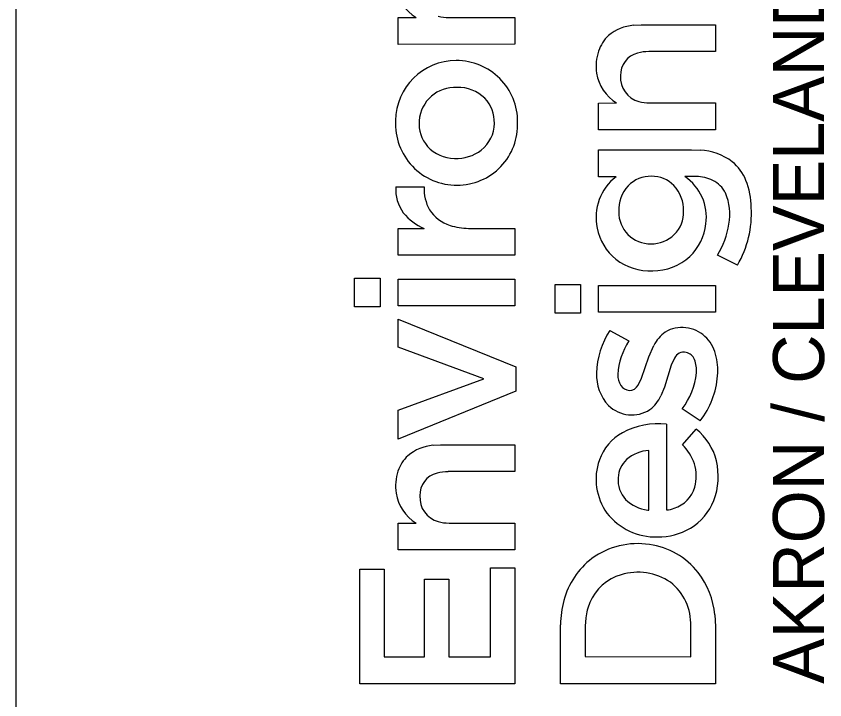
# Model space of a CAD drawing. Extents: x -0.4 to 34, y 0 to 22.
# Drawn here: x 32 to 32.901, y 3.12 to 3.882 of the extents above; entities that cross this region are included whole.
import ezdxf

# ---------------------------------------------------------------- set-up
doc = ezdxf.new("R2010")
doc.units = 0
doc.layers.add('SH_Border', color=7, linetype='Continuous')
doc.layers.add('SH_Cut_Line', color=7, linetype='Continuous')

msp = doc.modelspace()

# ---------------------------------------------------------------- linework, layer by layer
at = {"layer": 'SH_Border'}
msp.add_line((32, 0.5), (32, 21.5), dxfattribs=at)
at = {"layer": 'SH_Cut_Line'}
for p, q in [((32.42542, 3.88066), (32.44552, 3.88071)), ((32.42542, 3.85086), (32.42542, 3.88066)), ((32.48222, 3.88071), (32.55569, 3.88071)), ((32.55569, 3.88071), (32.55571, 3.85096)), ((32.68784, 3.8722), (32.69634, 3.87266)), ((32.69634, 3.87266), (32.77916, 3.87266)), ((32.77916, 3.87266), (32.77917, 3.84287)), ((32.55571, 3.85096), (32.42542, 3.85086)), ((32.77917, 3.84287), (32.70485, 3.8428)), ((32.64888, 3.7855), (32.66897, 3.78555)), ((32.64888, 3.75569), (32.64888, 3.7855)), ((32.70568, 3.78555), (32.77915, 3.78555)), ((32.77915, 3.78555), (32.77917, 3.75579)), ((32.77917, 3.75579), (32.64888, 3.75569)), ((32.6489, 3.70336), (32.64889, 3.73322)), ((32.64889, 3.73322), (32.75236, 3.73322)), ((32.75236, 3.73322), (32.76191, 3.73285)), ((32.66836, 3.70336), (32.6489, 3.70336)), ((32.75763, 3.70356), (32.74487, 3.70361)), ((32.42299, 3.69193), (32.45454, 3.69193)), ((32.42542, 3.64577), (32.45473, 3.64579)), ((32.42542, 3.61593), (32.42542, 3.64577)), ((32.50413, 3.64581), (32.55571, 3.64573)), ((32.55571, 3.64573), (32.55565, 3.61593)), ((32.55565, 3.61593), (32.42542, 3.61593)), ((32.8036, 3.60491), (32.7812, 3.61598)), ((32.37705, 3.55818), (32.37705, 3.59026)), ((32.37705, 3.59026), (32.40543, 3.59026)), ((32.40543, 3.59026), (32.40543, 3.55818)), ((32.42542, 3.55942), (32.42542, 3.58928)), ((32.42542, 3.58928), (32.55571, 3.58928)), ((32.55571, 3.58928), (32.55571, 3.55942)), ((32.60051, 3.55111), (32.60051, 3.58319)), ((32.60051, 3.58319), (32.62889, 3.58319)), ((32.62889, 3.58319), (32.62889, 3.55111)), ((32.64888, 3.55234), (32.64888, 3.5822)), ((32.64888, 3.5822), (32.77917, 3.5822)), ((32.77917, 3.5822), (32.77917, 3.55234)), ((32.55571, 3.55942), (32.42542, 3.55942)), ((32.40543, 3.55818), (32.37705, 3.55818)), ((32.62889, 3.55111), (32.60051, 3.55111)), ((32.77917, 3.55234), (32.64888, 3.55234)), ((32.42542, 3.51327), (32.42542, 3.5446)), ((32.42542, 3.5446), (32.5567, 3.4913)), ((32.66151, 3.53207), (32.68268, 3.52025)), ((32.70483, 3.50258), (32.71036, 3.51526)), ((32.52117, 3.47798), (32.42542, 3.51327)), ((32.69675, 3.47868), (32.70483, 3.50258)), ((32.73342, 3.50101), (32.72985, 3.4933)), ((32.5567, 3.4913), (32.5567, 3.46441)), ((32.72985, 3.4933), (32.72213, 3.46882)), ((32.42542, 3.44294), (32.52117, 3.47798)), ((32.69299, 3.47117), (32.69675, 3.47868)), ((32.72213, 3.46882), (32.71822, 3.45921)), ((32.5567, 3.46441), (32.42542, 3.41086)), ((32.42542, 3.41086), (32.42542, 3.44294)), ((32.76214, 3.43141), (32.74198, 3.44469)), ((32.72453, 3.42747), (32.72463, 3.33195)), ((32.74228, 3.40465), (32.75768, 3.422)), ((32.46439, 3.40397), (32.47289, 3.40443)), ((32.47289, 3.40443), (32.55571, 3.40443)), ((32.55571, 3.40443), (32.55571, 3.37465)), ((32.70489, 3.33182), (32.70489, 3.39834)), ((32.55571, 3.37465), (32.4814, 3.37457)), ((32.70361, 3.33165), (32.70489, 3.33182)), ((32.42542, 3.31728), (32.44552, 3.31733)), ((32.42542, 3.28747), (32.42542, 3.31728)), ((32.48222, 3.31733), (32.55569, 3.31733)), ((32.55569, 3.31733), (32.55571, 3.28756)), ((32.55571, 3.28756), (32.42542, 3.28747)), ((32.38298, 3.13791), (32.38298, 3.26598)), ((32.38298, 3.26598), (32.41012, 3.26598)), ((32.41012, 3.26598), (32.41012, 3.16827)), ((32.52857, 3.16827), (32.52857, 3.26722)), ((32.52857, 3.26722), (32.55571, 3.26722)), ((32.55571, 3.26722), (32.55571, 3.13791)), ((32.45503, 3.16827), (32.45503, 3.25488)), ((32.45503, 3.25488), (32.48218, 3.25488)), ((32.48218, 3.25488), (32.48218, 3.16827)), ((32.63465, 3.21178), (32.63407, 3.2023)), ((32.77847, 3.21497), (32.77917, 3.2021)), ((32.60643, 3.13799), (32.60644, 3.204)), ((32.63407, 3.2023), (32.63407, 3.16838)), ((32.75149, 3.16834), (32.75153, 3.20239)), ((32.77917, 3.2021), (32.77917, 3.138)), ((32.41012, 3.16827), (32.45503, 3.16827)), ((32.48218, 3.16827), (32.52857, 3.16827)), ((32.63407, 3.16838), (32.75149, 3.16834)), ((32.55571, 3.13791), (32.38298, 3.13791)), ((32.77917, 3.138), (32.60643, 3.13799))]:
    msp.add_line(p, q, dxfattribs=at)
for points in [[(32.42542, 3.85086), (32.42542, 3.88066), (32.44552, 3.88071)], [(32.48222, 3.88071), (32.55569, 3.88071), (32.55571, 3.85096), (32.42542, 3.85086)], [(32.68784, 3.8722), (32.69634, 3.87266), (32.77916, 3.87266), (32.77917, 3.84287), (32.70485, 3.8428)], [(32.64888, 3.75569), (32.64888, 3.7855), (32.66897, 3.78555)], [(32.70568, 3.78555), (32.77915, 3.78555), (32.77917, 3.75579), (32.64888, 3.75569)], [(32.66836, 3.70336), (32.6489, 3.70336), (32.64889, 3.73322), (32.75236, 3.73322), (32.76191, 3.73285)], [(32.75763, 3.70356), (32.74487, 3.70361)], [(32.42299, 3.69193), (32.45454, 3.69193)], [(32.50413, 3.64581), (32.55571, 3.64573), (32.55565, 3.61593), (32.42542, 3.61593)], [(32.42542, 3.61593), (32.42542, 3.64577), (32.45473, 3.64579)], [(32.8036, 3.60491), (32.7812, 3.61598)], [(32.66151, 3.53207), (32.68268, 3.52025)], [(32.69299, 3.47117), (32.69675, 3.47868), (32.70483, 3.50258), (32.71036, 3.51526)], [(32.73342, 3.50101), (32.72985, 3.4933), (32.72213, 3.46882), (32.71822, 3.45921)], [(32.76214, 3.43141), (32.74198, 3.44469)], [(32.72453, 3.42747), (32.72463, 3.33195)], [(32.74228, 3.40465), (32.75768, 3.422)], [(32.46439, 3.40397), (32.47289, 3.40443), (32.55571, 3.40443), (32.55571, 3.37465), (32.4814, 3.37457)], [(32.70361, 3.33165), (32.70489, 3.33182), (32.70489, 3.39834)], [(32.42542, 3.28747), (32.42542, 3.31728), (32.44552, 3.31733)], [(32.48222, 3.31733), (32.55569, 3.31733), (32.55571, 3.28756), (32.42542, 3.28747)], [(32.77847, 3.21497), (32.77917, 3.2021), (32.77917, 3.138), (32.60643, 3.13799)], [(32.63465, 3.21178), (32.63407, 3.2023), (32.63407, 3.16838), (32.75149, 3.16834), (32.75153, 3.20239)], [(32.60643, 3.13799), (32.60644, 3.204)]]:
    msp.add_lwpolyline(points, dxfattribs=at)
for points in [[(32.37705, 3.55818), (32.37705, 3.59026), (32.40543, 3.59026), (32.40543, 3.55818)], [(32.42542, 3.55942), (32.42542, 3.58928), (32.55571, 3.58928), (32.55571, 3.55942)], [(32.60051, 3.55111), (32.60051, 3.58319), (32.62889, 3.58319), (32.62889, 3.55111)], [(32.64888, 3.55234), (32.64888, 3.5822), (32.77917, 3.5822), (32.77917, 3.55234)], [(32.42542, 3.41086), (32.42542, 3.44294), (32.52117, 3.47798), (32.42542, 3.51327), (32.42542, 3.5446), (32.5567, 3.4913), (32.5567, 3.46441)], [(32.38298, 3.13791), (32.38298, 3.26598), (32.41012, 3.26598), (32.41012, 3.16827), (32.45503, 3.16827), (32.45503, 3.25488), (32.48218, 3.25488), (32.48218, 3.16827), (32.52857, 3.16827), (32.52857, 3.26722), (32.55571, 3.26722), (32.55571, 3.13791)]]:
    msp.add_lwpolyline(points, close=True, dxfattribs=at)
for centre, radius, start, end in [((32.47027, 3.92141), 0.04763, 188.96462, 238.69865), ((32.47027, 3.92141), 0.04763, 188.96462, 238.69865), ((32.48183, 3.92286), 0.04215, 254.08913, 270.52838), ((32.48183, 3.92286), 0.04215, 254.08913, 270.52838), ((32.69216, 3.82251), 0.04988, 94.97056, 130.22484), ((32.69216, 3.82251), 0.04988, 94.97056, 130.22484), ((32.68694, 3.83085), 0.04016, 132.22383, 161.68229), ((32.68694, 3.83085), 0.04016, 132.22383, 161.68229), ((32.70217, 3.82642), 0.05602, 162.27398, 187.79173), ((32.70217, 3.82642), 0.05602, 162.27398, 187.79173), ((32.69828, 3.81689), 0.02498, 103.68683, 182.21395), ((32.69828, 3.81689), 0.02498, 103.68683, 182.21395), ((32.70453, 3.79679), 0.04601, 89.60515, 105.33026), ((32.70453, 3.79679), 0.04601, 89.60515, 105.33026), ((32.49014, 3.76543), 0.0674, 89.84756, 179.64047), ((32.49014, 3.76543), 0.0674, 89.84756, 179.64047), ((32.49057, 3.76474), 0.0681, 359.54009, 90.21138), ((32.49057, 3.76474), 0.0681, 359.54009, 90.21138), ((32.69372, 3.82624), 0.04763, 188.96462, 238.69865), ((32.69372, 3.82624), 0.04763, 188.96462, 238.69865), ((32.7008, 3.81381), 0.02757, 175.58441, 255.13816), ((32.7008, 3.81381), 0.02757, 175.58441, 255.13816), ((32.48923, 3.76263), 0.0404, 87.04809, 175.57259), ((32.48923, 3.76263), 0.0404, 87.04809, 175.57259), ((32.49204, 3.75999), 0.04299, 45.84264, 90.98008), ((32.49204, 3.75999), 0.04299, 45.84264, 90.98008), ((32.49458, 3.76421), 0.03821, 357.88569, 44.15902), ((32.49458, 3.76421), 0.03821, 357.88569, 44.15902), ((32.70529, 3.82769), 0.04215, 254.08913, 270.52838), ((32.70529, 3.82769), 0.04215, 254.08913, 270.52838), ((32.49083, 3.76209), 0.06819, 176.8344, 270.40384), ((32.49083, 3.76209), 0.06819, 176.8344, 270.40384), ((32.48729, 3.7625), 0.03848, 175.15378, 221.14706), ((32.48729, 3.7625), 0.03848, 175.15378, 221.14706), ((32.49123, 3.76139), 0.06749, 270.06243, 2.37759), ((32.49123, 3.76139), 0.06749, 270.06243, 2.37759), ((32.49446, 3.76318), 0.0383, 308.28936, 359.43468), ((32.49446, 3.76318), 0.0383, 308.28936, 359.43468), ((32.48919, 3.76607), 0.04228, 223.09994, 268.80895), ((32.48919, 3.76607), 0.04228, 223.09994, 268.80895), ((32.49096, 3.7679), 0.04418, 266.56515, 308.06078), ((32.49096, 3.7679), 0.04418, 266.56515, 308.06078), ((32.75907, 3.66789), 0.06503, 53.40344, 87.49062), ((32.75907, 3.66789), 0.06503, 53.40344, 87.49062), ((32.76517, 3.68039), 0.05141, 21.60748, 50.5577), ((32.76517, 3.68039), 0.05141, 21.60748, 50.5577), ((32.70292, 3.65813), 0.05692, 127.37482, 192.22468), ((32.70292, 3.65813), 0.05692, 127.37482, 192.22468), ((32.70693, 3.66927), 0.0346, 88.47302, 136.42562), ((32.70693, 3.66927), 0.0346, 88.47302, 136.42562), ((32.70814, 3.66963), 0.03424, 44.27195, 90.47623), ((32.70814, 3.66963), 0.03424, 44.27195, 90.47623), ((32.71421, 3.65829), 0.05472, 352.1125, 55.92295), ((32.71421, 3.65829), 0.05472, 352.1125, 55.92295), ((32.75666, 3.65725), 0.04633, 65.01687, 88.8011), ((32.75666, 3.65725), 0.04633, 65.01687, 88.8011), ((32.7626, 3.67155), 0.03085, 26.26808, 63.80301), ((32.7626, 3.67155), 0.03085, 26.26808, 63.80301), ((32.73069, 3.66714), 0.08835, 1.15143, 21.3627), ((32.73069, 3.66714), 0.08835, 1.15143, 21.3627), ((32.46616, 3.68882), 0.04329, 175.87313, 216.34747), ((32.46616, 3.68882), 0.04329, 175.87313, 216.34747), ((32.50087, 3.68948), 0.04639, 176.9688, 209.60636), ((32.50087, 3.68948), 0.04639, 176.9688, 209.60636), ((32.71141, 3.66602), 0.0401, 137.46739, 182.33237), ((32.71141, 3.66602), 0.0401, 137.46739, 182.33237), ((32.70368, 3.666), 0.03996, 358.57141, 43.53765), ((32.70368, 3.666), 0.03996, 358.57141, 43.53765), ((32.73565, 3.66154), 0.05953, 349.30734, 23.43071), ((32.73565, 3.66154), 0.05953, 349.30734, 23.43071), ((32.70538, 3.66244), 0.11383, 329.6388, 3.25998), ((32.70538, 3.66244), 0.11383, 329.6388, 3.25998), ((32.47466, 3.69716), 0.05511, 218.09809, 248.7907), ((32.47466, 3.69716), 0.05511, 218.09809, 248.7907), ((32.49514, 3.68814), 0.04079, 211.94466, 253.2028), ((32.49514, 3.68814), 0.04079, 211.94466, 253.2028), ((32.70645, 3.6637), 0.03511, 178.88208, 271.08374), ((32.70645, 3.6637), 0.03511, 178.88208, 271.08374), ((32.70818, 3.66404), 0.03546, 268.27882, 1.55016), ((32.70818, 3.66404), 0.03546, 268.27882, 1.55016), ((32.50465, 3.7165), 0.07069, 252.46555, 269.57296), ((32.50465, 3.7165), 0.07069, 252.46555, 269.57296), ((32.70988, 3.65708), 0.05887, 313.74196, 353.8554), ((32.70988, 3.65708), 0.05887, 313.74196, 353.8554), ((32.70738, 3.66334), 0.08771, 327.31495, 351.57478), ((32.70738, 3.66334), 0.08771, 327.31495, 351.57478), ((32.70463, 3.65696), 0.05837, 190.75182, 231.28919), ((32.70463, 3.65696), 0.05837, 190.75182, 231.28919), ((32.70954, 3.65901), 0.06051, 269.6361, 312.70877), ((32.70954, 3.65901), 0.06051, 269.6361, 312.70877), ((32.70632, 3.66112), 0.06269, 232.46061, 272.59022), ((32.70632, 3.66112), 0.06269, 232.46061, 272.59022), ((32.73636, 3.48258), 0.08973, 146.53104, 178.7571), ((32.73636, 3.48258), 0.08973, 146.53104, 178.7571), ((32.7406, 3.5026), 0.03263, 80.17192, 122.51969), ((32.7406, 3.5026), 0.03263, 80.17192, 122.51969), ((32.74278, 3.49824), 0.03667, 47.79344, 84.68918), ((32.74278, 3.49824), 0.03667, 47.79344, 84.68918), ((32.74661, 3.49713), 0.04053, 125.51182, 153.41595), ((32.74661, 3.49713), 0.04053, 125.51182, 153.41595), ((32.73788, 3.4946), 0.04267, 14.9966, 46.20632), ((32.73788, 3.4946), 0.04267, 14.9966, 46.20632), ((32.74519, 3.4789), 0.07495, 146.51121, 176.91007), ((32.74519, 3.4789), 0.07495, 146.51121, 176.91007), ((32.74384, 3.49631), 0.01143, 76.66094, 155.7053), ((32.74384, 3.49631), 0.01143, 76.66094, 155.7053), ((32.74397, 3.49511), 0.01256, 21.5098, 78.52618), ((32.74397, 3.49511), 0.01256, 21.5098, 78.52618), ((32.71044, 3.48674), 0.07121, 355.83062, 15.39138), ((32.71044, 3.48674), 0.07121, 355.83062, 15.39138), ((32.72592, 3.48766), 0.03209, 354.57264, 22.06805), ((32.72592, 3.48766), 0.03209, 354.57264, 22.06805), ((32.69666, 3.48238), 0.05005, 177.53659, 222.79318), ((32.69666, 3.48238), 0.05005, 177.53659, 222.79318), ((32.6931, 3.48233), 0.02276, 178.47474, 211.08679), ((32.6931, 3.48233), 0.02276, 178.47474, 211.08679), ((32.68248, 3.49149), 0.0757, 321.81101, 354.79685), ((32.68248, 3.49149), 0.0757, 321.81101, 354.79685), ((32.68952, 3.4882), 0.09219, 321.9777, 355.87384), ((32.68952, 3.4882), 0.09219, 321.9777, 355.87384), ((32.68331, 3.4767), 0.01148, 212.23676, 268.37769), ((32.68331, 3.4767), 0.01148, 212.23676, 268.37769), ((32.68342, 3.47589), 0.01067, 267.71603, 333.73375), ((32.68342, 3.47589), 0.01067, 267.71603, 333.73375), ((32.68098, 3.4758), 0.04077, 308.08772, 335.98736), ((32.68098, 3.4758), 0.04077, 308.08772, 335.98736), ((32.68599, 3.47535), 0.0375, 225.98539, 302.47965), ((32.68599, 3.47535), 0.0375, 225.98539, 302.47965), ((32.7152, 3.34414), 0.08384, 83.61499, 118.28755), ((32.7152, 3.34414), 0.08384, 83.61499, 118.28755), ((32.70239, 3.36906), 0.05583, 118.83082, 160.62438), ((32.70239, 3.36906), 0.05583, 118.83082, 160.62438), ((32.71744, 3.37167), 0.06443, 13.53365, 51.36148), ((32.71744, 3.37167), 0.06443, 13.53365, 51.36148), ((32.46871, 3.35428), 0.04988, 94.96958, 130.22249), ((32.46871, 3.35428), 0.04988, 94.96958, 130.22249), ((32.70785, 3.35609), 0.04235, 94.00805, 130.88169), ((32.70785, 3.35609), 0.04235, 94.00805, 130.88169), ((32.70378, 3.36556), 0.05486, 19.03571, 45.44059), ((32.70378, 3.36556), 0.05486, 19.03571, 45.44059), ((32.46348, 3.36263), 0.04015, 132.22192, 161.68183), ((32.46348, 3.36263), 0.04015, 132.22192, 161.68183), ((32.71041, 3.36612), 0.06437, 160.52012, 215.78311), ((32.71041, 3.36612), 0.06437, 160.52012, 215.78311), ((32.70048, 3.36628), 0.02985, 132.98507, 177.179), ((32.70048, 3.36628), 0.02985, 132.98507, 177.179), ((32.71069, 3.3697), 0.047, 344.60586, 17.007), ((32.71069, 3.3697), 0.047, 344.60586, 17.007), ((32.70635, 3.36921), 0.07579, 339.3542, 13.37853), ((32.70635, 3.36921), 0.07579, 339.3542, 13.37853), ((32.47872, 3.35819), 0.05601, 162.27355, 187.79185), ((32.47872, 3.35819), 0.05601, 162.27355, 187.79185), ((32.47482, 3.34867), 0.02498, 103.68646, 182.21874), ((32.47482, 3.34867), 0.02498, 103.68646, 182.21874), ((32.48108, 3.32856), 0.04601, 89.60494, 105.3284), ((32.48108, 3.32856), 0.04601, 89.60494, 105.3284), ((32.7017, 3.36503), 0.03115, 175.00126, 223.28301), ((32.7017, 3.36503), 0.03115, 175.00126, 223.28301), ((32.7224, 3.36715), 0.03504, 288.00773, 343.55078), ((32.7224, 3.36715), 0.03504, 288.00773, 343.55078), ((32.47026, 3.35802), 0.04762, 188.96199, 238.70369), ((32.47026, 3.35802), 0.04762, 188.96199, 238.70369), ((32.47735, 3.34558), 0.02756, 175.58538, 255.14386), ((32.47735, 3.34558), 0.02756, 175.58538, 255.14386), ((32.70891, 3.37363), 0.04231, 225.06188, 262.79738), ((32.70891, 3.37363), 0.04231, 225.06188, 262.79738), ((32.71894, 3.3652), 0.0626, 300.94269, 338.73225), ((32.71894, 3.3652), 0.0626, 300.94269, 338.73225), ((32.72474, 3.35216), 0.02021, 269.7003, 294.8711), ((32.72474, 3.35216), 0.02021, 269.7003, 294.8711), ((32.71253, 3.37054), 0.06872, 217.74516, 271.65431), ((32.71253, 3.37054), 0.06872, 217.74516, 271.65431), ((32.48183, 3.35948), 0.04215, 254.09162, 270.52835), ((32.48183, 3.35948), 0.04215, 254.09162, 270.52835), ((32.71549, 3.37241), 0.07056, 269.20477, 300.33412), ((32.71549, 3.37241), 0.07056, 269.20477, 300.33412), ((32.69229, 3.20792), 0.08641, 81.19402, 125.99844), ((32.69229, 3.20792), 0.08641, 81.19402, 125.99844), ((32.69458, 3.21132), 0.08272, 37.85208, 82.40204), ((32.69458, 3.21132), 0.08272, 37.85208, 82.40204), ((32.69387, 3.20893), 0.08654, 127.23621, 165.14796), ((32.69387, 3.20893), 0.08654, 127.23621, 165.14796), ((32.69279, 3.19862), 0.06389, 55.67272, 107.20935), ((32.69279, 3.19862), 0.06389, 55.67272, 107.20935), ((32.68586, 3.20567), 0.09308, 5.73329, 37.30396), ((32.68586, 3.20567), 0.09308, 5.73329, 37.30396), ((32.68893, 3.20782), 0.05398, 106.18808, 157.38609), ((32.68893, 3.20782), 0.05398, 106.18808, 157.38609), ((32.69291, 3.20499), 0.05867, 357.46616, 52.26647), ((32.69291, 3.20499), 0.05867, 357.46616, 52.26647), ((32.71426, 3.20281), 0.10783, 164.7861, 179.37039), ((32.71426, 3.20281), 0.10783, 164.7861, 179.37039), ((32.69829, 3.20389), 0.06412, 157.35705, 172.92755), ((32.69829, 3.20389), 0.06412, 157.35705, 172.92755)]:
    msp.add_arc(centre, radius, start, end, dxfattribs=at)

# ---------------------------------------------------------------- texts
msp.add_text('AKRON / CLEVELAND / COLUMBUS', height=0.056969, rotation=90, dxfattribs=at).set_placement((32.90012, 3.138))

doc.saveas('drawing.dxf')
